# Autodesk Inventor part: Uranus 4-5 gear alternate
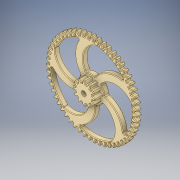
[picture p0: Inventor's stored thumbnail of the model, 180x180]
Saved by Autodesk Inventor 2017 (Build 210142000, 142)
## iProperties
Created: 2016-05
Part Number: Uranus 4-5 gear alternate
Material: Generic
Document SubType Name: Modeling
Designer: Stan
Density: 1 g/cm^3
Appearance: Beige
Author: Stan
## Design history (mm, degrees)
sketch "Sketch1"
  geometry: A1 r 23.475 centre (28.603, -44.634) between (6.935, -53.666) and (9.151, -57.774); A2 r 23.475 centre (28.603, -44.634) between (6.935, -53.666) and (9.151, -57.774); A3 r 23.475 centre (-17.75, -49.952) between (4.173, -58.345) and (5.4, -53.842); A4 r 23.475 centre (-17.75, -49.952) between (4.173, -58.345) and (5.4, -53.842); A5 r 23.475 centre (33.504, -41.082) between (13.008, -52.526) and (15.677, -56.354); A6 r 23.475 centre (33.504, -41.082) between (13.008, -52.526) and (15.677, -56.354); A7 r 23.475 centre (-11.94, -51.65) between (10.797, -57.489) and (11.502, -52.876); A8 r 23.475 centre (-11.94, -51.65) between (10.797, -57.489) and (11.502, -52.876); A9 r 23.475 centre (37.969, -36.995) between (18.91, -50.701) and (21.998, -54.2); A10 r 23.475 centre (37.969, -36.995) between (18.91, -50.701) and (21.998, -54.2); A11 r 23.475 centre (-5.975, -52.674) between (17.28, -55.884) and (17.455, -51.22); A12 r 23.475 centre (-5.975, -52.674) between (17.28, -55.884) and (17.455, -51.22); A13 r 23.475 centre (41.939, -32.426) between (24.566, -48.214) and (28.033, -51.339); A14 r 23.475 centre (41.939, -32.426) between (24.566, -48.214) and (28.033, -51.339); A15 r 23.475 centre (0.069, -53.012) between (23.537, -53.55) and (23.18, -48.896); A16 r 23.475 centre (0.069, -53.012) between (23.537, -53.55) and (23.18, -48.896); A17 r 23.475 centre (45.362, -27.434) between (29.902, -45.1) and (33.703, -47.809); A18 r 23.475 centre (45.362, -27.434) between (29.902, -45.1) and (33.703, -47.809); A19 r 23.475 centre (6.111, -52.659) between (29.488, -50.518) and (28.602, -45.935); A20 r 23.475 centre (6.111, -52.659) between (29.488, -50.518) and (28.602, -45.935); A21 r 23.475 centre (48.193, -22.084) between (34.848, -41.397) and (38.933, -43.656); A22 r 23.475 centre (48.193, -22.084) between (34.848, -41.397) and (38.933, -43.656); A23 r 23.475 centre (12.074, -51.619) between (35.054, -46.827) and (33.652, -42.375); A24 r 23.475 centre (12.074, -51.619) between (35.054, -46.827) and (33.652, -42.375); A25 r 23.475 centre (50.396, -16.447) between (39.34, -37.155) and (43.656, -38.933); A26 r 23.475 centre (50.396, -16.447) between (39.34, -37.155) and (43.656, -38.933); A27 r 23.475 centre (17.879, -49.906) between (40.164, -42.526) and (38.263, -38.263); A28 r 23.475 centre (17.879, -49.906) between (40.164, -42.526) and (38.263, -38.263); A29 r 23.475 centre (51.943, -10.595) between (43.319, -32.428) and (47.809, -33.703); A30 r 23.475 centre (51.943, -10.595) between (43.319, -32.428) and (47.809, -33.703); A31 r 23.475 centre (23.452, -47.543) between (44.75, -37.67) and (42.375, -33.652); A32 r 23.475 centre (23.452, -47.543) between (44.75, -37.67) and (42.375, -33.652); A33 r 23.475 centre (52.812, -4.605) between (46.733, -27.279) and (51.339, -28.033); A34 r 23.475 centre (52.812, -4.605) between (46.733, -27.279) and (51.339, -28.033); A35 r 23.475 centre (28.718, -44.56) between (48.752, -32.324) and (45.935, -28.602); A36 r 23.475 centre (28.718, -44.56) between (48.752, -32.324) and (45.935, -28.602); A37 r 23.475 centre (52.993, 1.445) between (49.538, -21.774) and (54.2, -21.998); A38 r 23.475 centre (52.993, 1.445) between (49.538, -21.774) and (54.2, -21.998); A39 r 23.475 centre (33.61, -40.996) between (52.119, -26.556) and (48.896, -23.18); A40 r 23.475 centre (33.61, -40.996) between (52.119, -26.556) and (48.896, -23.18); A41 r 23.475 centre (52.482, 7.477) between (51.697, -15.985) and (56.354, -15.677); A42 r 23.475 centre (52.482, 7.477) between (51.697, -15.985) and (56.354, -15.677); A43 r 23.475 centre (38.065, -36.897) between (54.806, -20.442) and (51.22, -17.455); A44 r 23.475 centre (38.065, -36.897) between (54.806, -20.442) and (51.22, -17.455); A45 r 23.475 centre (51.288, 13.41) between (53.183, -9.988) and (57.774, -9.151); A46 r 23.475 centre (51.288, 13.41) between (53.183, -9.988) and (57.774, -9.151); A47 r 23.475 centre (42.022, -32.317) between (56.779, -14.061) and (52.876, -11.502); A48 r 23.475 centre (42.022, -32.317) between (56.779, -14.061) and (52.876, -11.502); A49 r 23.475 centre (49.425, 19.169) between (53.974, -3.86) and (58.441, -2.505); A50 r 23.475 centre (49.425, 19.169) between (53.974, -3.86) and (58.441, -2.505); A51 r 23.475 centre (45.432, -27.317) between (58.012, -7.497) and (53.842, -5.4); A52 r 23.475 centre (45.432, -27.317) between (58.012, -7.497) and (53.842, -5.4); A53 r 23.475 centre (46.918, 24.678) between (54.063, 2.317) and (58.345, 4.173); A54 r 23.475 centre (46.918, 24.678) between (54.063, 2.317) and (58.345, 4.173); A55 r 23.475 centre (48.25, -21.96) between (58.488, -0.835) and (54.107, 0.773); A56 r 23.475 centre (48.25, -21.96) between (58.488, -0.835) and (54.107, 0.773); A57 r 23.475 centre (43.799, 29.866) between (53.446, 8.465) and (57.489, 10.797); A58 r 23.475 centre (43.799, 29.866) between (53.446, 8.465) and (57.489, 10.797); A59 r 23.475 centre (50.439, -16.316) between (58.202, 5.837) and (53.666, 6.935); A60 r 23.475 centre (50.439, -16.316) between (58.202, 5.837) and (53.666, 6.935); A61 r 23.475 centre (40.109, 34.664) between (52.133, 14.502) and (55.884, 17.28); A62 r 23.475 centre (40.109, 34.664) between (52.133, 14.502) and (55.884, 17.28); A63 r 23.475 centre (51.97, -10.46) between (57.158, 12.434) and (52.526, 13.008); A64 r 23.475 centre (51.97, -10.46) between (57.158, 12.434) and (52.526, 13.008)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; 1 further point
  constraints: 880 point on circle, 440 centre point, 8 horizontal alignment, 1312 other
extrude "Extrusion1" new body sketch "Sketch1" distance "d0" = 6.35; taper "d1" = 0 deg
sketch "Sketch2"
  geometry: A1 r 9.162 centre (-11.844, -1.207) between (-8.219, 7.208) and (-11.906, 7.956); A2 r 9.162 centre (-11.844, -1.207) between (-8.219, 7.208) and (-11.906, 7.956); A3 r 9.162 centre (1.207, 11.844) between (-7.956, 11.906) and (-7.208, 8.219); A4 r 9.162 centre (1.207, 11.844) between (-7.956, 11.906) and (-7.208, 8.219); A5 r 9.162 centre (-9.654, -6.967) between (-10.722, 2.133) and (-14.289, 0.937); A6 r 9.162 centre (-9.654, -6.967) between (-10.722, 2.133) and (-14.289, 0.937); A7 r 9.162 centre (-4.877, 10.861) between (-12.843, 6.333) and (-10.352, 3.514); A8 r 9.162 centre (-4.877, 10.861) between (-12.843, 6.333) and (-10.352, 3.514); A9 r 9.162 centre (-4.877, -10.861) between (-10.352, -3.514) and (-12.843, -6.333); A10 r 9.162 centre (-4.877, -10.861) between (-10.352, -3.514) and (-12.843, -6.333); A11 r 9.162 centre (-9.654, 6.967) between (-14.289, -0.937) and (-10.722, -2.133); A12 r 9.162 centre (-9.654, 6.967) between (-14.289, -0.937) and (-10.722, -2.133); A13 r 9.162 centre (1.207, -11.844) between (-7.208, -8.219) and (-7.956, -11.906); A14 r 9.162 centre (1.207, -11.844) between (-7.208, -8.219) and (-7.956, -11.906); A15 r 9.162 centre (-11.844, 1.207) between (-11.906, -7.956) and (-8.219, -7.208); A16 r 9.162 centre (-11.844, 1.207) between (-11.906, -7.956) and (-8.219, -7.208); A17 r 9.162 centre (6.967, -9.654) between (-2.133, -10.722) and (-0.937, -14.289); A18 r 9.162 centre (6.967, -9.654) between (-2.133, -10.722) and (-0.937, -14.289); A19 r 9.162 centre (-10.861, -4.877) between (-6.333, -12.843) and (-3.514, -10.352); A20 r 9.162 centre (-10.861, -4.877) between (-6.333, -12.843) and (-3.514, -10.352); A21 r 9.162 centre (10.861, -4.877) between (3.514, -10.352) and (6.333, -12.843); A22 r 9.162 centre (10.861, -4.877) between (3.514, -10.352) and (6.333, -12.843); A23 r 9.162 centre (-6.967, -9.654) between (0.937, -14.289) and (2.133, -10.722); A24 r 9.162 centre (-6.967, -9.654) between (0.937, -14.289) and (2.133, -10.722); A25 r 9.162 centre (11.844, 1.207) between (8.219, -7.208) and (11.906, -7.956); A26 r 9.162 centre (11.844, 1.207) between (8.219, -7.208) and (11.906, -7.956); A27 r 9.162 centre (-1.207, -11.844) between (7.956, -11.906) and (7.208, -8.219); A28 r 9.162 centre (-1.207, -11.844) between (7.956, -11.906) and (7.208, -8.219); A29 r 9.162 centre (9.654, 6.967) between (10.722, -2.133) and (14.289, -0.937); A30 r 9.162 centre (9.654, 6.967) between (10.722, -2.133) and (14.289, -0.937); A31 r 9.162 centre (4.877, -10.861) between (12.843, -6.333) and (10.352, -3.514); A32 r 9.162 centre (4.877, -10.861) between (12.843, -6.333) and (10.352, -3.514); A33 r 9.162 centre (4.877, 10.861) between (10.352, 3.514) and (12.843, 6.333); A34 r 9.162 centre (4.877, 10.861) between (10.352, 3.514) and (12.843, 6.333); A35 r 9.162 centre (9.654, -6.967) between (14.289, 0.937) and (10.722, 2.133); A36 r 9.162 centre (9.654, -6.967) between (14.289, 0.937) and (10.722, 2.133); A37 r 9.162 centre (-1.207, 11.844) between (7.208, 8.219) and (7.956, 11.906); A38 r 9.162 centre (-1.207, 11.844) between (7.208, 8.219) and (7.956, 11.906); A39 r 9.162 centre (11.844, -1.207) between (11.906, 7.956) and (8.219, 7.208); A40 r 9.162 centre (11.844, -1.207) between (11.906, 7.956) and (8.219, 7.208); A41 r 9.162 centre (-6.967, 9.654) between (2.133, 10.722) and (0.937, 14.289); A42 r 9.162 centre (-6.967, 9.654) between (2.133, 10.722) and (0.937, 14.289); A43 r 9.162 centre (10.861, 4.877) between (6.333, 12.843) and (3.514, 10.352); A44 r 9.162 centre (10.861, 4.877) between (6.333, 12.843) and (3.514, 10.352); A45 r 9.162 centre (1.207, 11.844) between (-7.956, 11.906) and (-7.208, 8.219); A46 r 9.162 centre (-11.844, -1.207) between (-8.219, 7.208) and (-11.906, 7.956); A47 r 9.162 centre (-4.877, 10.861) between (-12.843, 6.333) and (-10.352, 3.514); A48 r 9.162 centre (-9.654, -6.967) between (-10.722, 2.133) and (-14.289, 0.937); A49 r 9.162 centre (-9.654, 6.967) between (-14.289, -0.937) and (-10.722, -2.133); A50 r 9.162 centre (-4.877, -10.861) between (-10.352, -3.514) and (-12.843, -6.333); A51 r 9.162 centre (-11.844, 1.207) between (-11.906, -7.956) and (-8.219, -7.208); A52 r 9.162 centre (1.207, -11.844) between (-7.208, -8.219) and (-7.956, -11.906); A53 r 9.162 centre (-10.861, -4.877) between (-6.333, -12.843) and (-3.514, -10.352); A54 r 9.162 centre (6.967, -9.654) between (-2.133, -10.722) and (-0.937, -14.289); A55 r 9.162 centre (-6.967, -9.654) between (0.937, -14.289) and (2.133, -10.722); A56 r 9.162 centre (10.861, -4.877) between (3.514, -10.352) and (6.333, -12.843); A57 r 9.162 centre (-1.207, -11.844) between (7.956, -11.906) and (7.208, -8.219); A58 r 9.162 centre (11.844, 1.207) between (8.219, -7.208) and (11.906, -7.956); A59 r 9.162 centre (4.877, -10.861) between (12.843, -6.333) and (10.352, -3.514); A60 r 9.162 centre (9.654, 6.967) between (10.722, -2.133) and (14.289, -0.937); A61 r 9.162 centre (9.654, -6.967) between (14.289, 0.937) and (10.722, 2.133); A62 r 9.162 centre (4.877, 10.861) between (10.352, 3.514) and (12.843, 6.333); A63 r 9.162 centre (11.844, -1.207) between (11.906, 7.956) and (8.219, 7.208); A64 r 9.162 centre (-1.207, 11.844) between (7.208, 8.219) and (7.956, 11.906)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; 1 further point; 48 other entities
  constraints: 192 point on circle, 96 centre point, 8 horizontal alignment, 8 vertical alignment, 272 other
extrude "Extrusion2" join sketch "Sketch2" distance "d2" = 9.525; taper "d3" = 0 deg
sketch "Sketch3"
  geometry: C1 r 3.175 at (0, 0); 1 further point
  constraints: 1 centre point, 1 coincident
  dimensions: "d4" = 6.35 diameter of C1
extrude "Extrusion3" cut sketch "Sketch3" distance "d5" = 15.875; taper "d6" = 0 deg; dims "d12" = 3.175, "d13" = 0
sketch "Sketch4"
  geometry: A1 r 51.942 centre (0, 0) between (43.338, -28.633) and (51.099, 9.321); A2 r 51.942 centre (0, 0) between (40.624, 32.369) and (6.926, 51.479); A3 r 51.942 centre (0, 0) between (-18.231, 48.638) and (-46.819, 22.495); A4 r 51.942 centre (0, 0) between (-51.891, -2.309) and (-35.862, -37.576); A5 r 51.942 centre (0, 0) between (-13.84, -50.065) and (24.655, -45.718); A6 r 32.931 centre (12.286, 30.006) between (-16.296, 46.363) and (-14.27, 10.531); A7 r 24.19 centre (13.278, 28.277) between (6.253, 51.424) and (-7.759, 16.337); A8 r 32.931 centre (-24.741, 20.957) between (-49.13, -1.171) and (-14.425, -10.317); A9 r 24.19 centre (-22.79, 21.367) between (-46.975, 21.838) and (-17.935, -2.331); A10 r 32.931 centre (-27.576, -17.054) between (-14.068, -47.087) and (5.354, -16.907); A11 r 24.19 centre (-27.363, -15.072) between (-35.285, -37.928) and (-3.326, -17.778); A12 r 32.931 centre (7.698, -31.497) between (40.435, -27.93) and (17.734, -0.133); A13 r 24.19 centre (5.879, -30.682) between (25.168, -45.279) and (15.88, -8.656); A14 r 32.931 centre (32.334, -2.412) between (39.058, 29.825) and (5.606, 16.826); A15 r 24.19 centre (30.997, -3.89) between (50.84, 9.944) and (13.14, 12.428); A16 r 16.683 centre (0, 0) between (3.943, 16.21) and (-5.824, 15.633); A17 r 16.683 centre (0, 0) between (16.635, 1.26) and (13.068, 10.37); A18 r 16.683 centre (0, 0) between (6.338, -15.432) and (13.901, -9.224); A19 r 16.683 centre (0, 0) between (-14.199, 8.759) and (-16.668, -0.708); A20 r 16.683 centre (0, 0) between (-12.718, -10.797) and (-4.477, -16.071); A21 r 1.588 centre (-18.254, -0.776) between (-17.935, -2.331) and (-16.668, -0.708); A22 r 1.587 centre (-15.55, 9.592) between (-14.199, 8.759) and (-14.27, 10.531); A23 r 1.587 centre (-17.674, 47.152) between (-16.296, 46.363) and (-18.231, 48.638); A24 r 1.587 centre (-45.388, 21.807) between (-46.819, 22.495) and (-46.975, 21.838); A25 r 1.587 centre (-6.379, 17.121) between (-7.759, 16.337) and (-5.824, 15.633); A26 r 1.588 centre (6.714, 49.905) between (6.926, 51.479) and (6.253, 51.424); A27 r 1.588 centre (39.382, 31.379) between (39.058, 29.825) and (40.624, 32.369); A28 r 1.588 centre (4.318, 17.753) between (3.943, 16.21) and (5.606, 16.826); A29 r 1.588 centre (14.312, 11.357) between (13.14, 12.428) and (13.068, 10.37); A30 r 1.588 centre (49.538, 9.036) between (51.099, 9.321) and (50.84, 9.944); A31 r 1.588 centre (42.013, -27.758) between (40.435, -27.93) and (43.338, -28.633); A32 r 1.588 centre (18.218, 1.379) between (16.635, 1.26) and (17.734, -0.133); A33 r 1.588 centre (15.224, -10.102) between (15.88, -8.656) and (13.901, -9.224); A34 r 1.587 centre (6.942, -16.9) between (6.338, -15.432) and (5.354, -16.907); A35 r 1.588 centre (-13.417, -48.535) between (-14.068, -47.087) and (-13.84, -50.065); A36 r 1.588 centre (23.902, -44.321) between (24.655, -45.718) and (25.168, -45.279); A37 r 1.587 centre (-34.766, -36.428) between (-35.862, -37.576) and (-35.285, -37.928); A38 r 1.587 centre (-50.305, -2.238) between (-49.13, -1.171) and (-51.891, -2.309); A39 r 1.588 centre (-13.928, -11.824) between (-12.718, -10.797) and (-14.425, -10.317); A40 r 1.588 centre (-4.903, -17.6) between (-3.326, -17.778) and (-4.477, -16.071); 1 further point
  constraints: 80 point on circle, 40 centre point, 40 tangent, 19 equal radius, 1 coincident
  dimensions: "d9" = 1.5875 radius of A21
extrude "Extrusion4" cut sketch "Sketch4" distance "d7" = 6.35; taper "d8" = 0 deg
fillet "Fillet1" dims "d10" = 0.79375
fillet "Fillet2" dims "d11" = 0.79375
fillet "Fillet3" dims "d14" = 0.79375
fillet "Fillet4" dims "d15" = 0.79375
fillet "Fillet5" dims "d16" = 0.79375
fillet "Fillet6" dims "d17" = 0.79375
fillet "Fillet7" dims "d18" = 0.79375
fillet "Fillet8" dims "d19" = 0.79375
fillet "Fillet9" dims "d20" = 0.79375
body "Solid1"
